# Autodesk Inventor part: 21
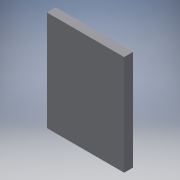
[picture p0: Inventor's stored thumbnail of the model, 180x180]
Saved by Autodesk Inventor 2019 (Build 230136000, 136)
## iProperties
Created: 2019-01
Part Number: 21
Material: Generic
Document SubType Name: Modeling
Designer: Guy Link
Density: 1 g/cm^3
Appearance: Default
Author: Guy Link
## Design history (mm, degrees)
sketch "Sketch1"
  geometry: L1 (0, 0)-(-27.432, 0); L2 (-27.432, 0)-(-27.432, 35.56); L3 (-27.432, 35.56)-(0, 35.56); L4 (0, 35.56)-(0, 0)
  constraints: 8 end point, 2 parallel, 1 horizontal, 1 perpendicular
  dimensions: "d2" = 27.432 distance of L2.end L3.end; "d3" = 35.56 distance of L1.end L2.end
extrude "Extrusion1" new body sketch "Sketch1" distance "d0" = 3.175; taper "d1" = 0 deg
body "Solid1"
